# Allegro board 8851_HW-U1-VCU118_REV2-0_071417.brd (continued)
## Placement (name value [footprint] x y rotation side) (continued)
U53  SN74AVC1T45  [SC70_6]  131.13 15.57 180 top
U57  SI5328B  [QFN36_6X6MM]  85.08 23.6 270 top
U60  -  [MT40A256M16GE-083E]  74.76 38.64 270 bottom
U61  -  [MT40A256M16GE-083E]  74.76 66.84 270 bottom
U62  -  [MT40A256M16GE-083E]  74.76 95.03 270 bottom
U63  -  [MT40A256M16GE-083E]  74.76 80.93 270 bottom
U64  -  [MT40A256M16GE-083E]  74.76 52.74 270 bottom
U71  NC7SV125  [SC70_5]  190.97 168.46 90 bottom
U80  TCA9548APWR  [TSSOP_24]  138.89 119.9 180 top
U104  SI53340-B-GM  [QFN16_SI_3X3MM]  106.39 23.87 90 top
U109  NVT2008PW  [TSSOP_20]  26.73 120.91 270 bottom
U111  XC7Z010CLG225  [CL225]  15.9 134.57 270 top
U114  N25Q128A  [SO16_50P300X413]  18.61 110.08 270 bottom
U115  -  [DIGILENT_USB_JTAG_2_NC]  13.65 162.11 180 top
U122  SI5335A-B02436-GM  [QFN24_4X4MM]  164.54 19.5 270 top
U123  FS1-Z38-20Z6-10  [ON_AMP_FSI_Z38_20Z6_10]  50.72 51.21 270 top
U124  MAX15053  [WLP_9]  13.9 117.79 0 top
U125  MAX15027  [TDFN_10_3X3_EP]  39.5 106.17 180 bottom
U128  MAX16050  [TQFN_28_EP]  31.75 110.95 90 bottom
U131  MAX8892EXK+T  [SC70_5]  10.85 67.41 0 bottom
U132  NC7SZ66P5X  [SC70_5]  139.64 153.77 270 bottom
U133  MT25QU01  [SO16_50P300X413]  150.37 21.74 0 top
U134  TPS51200DRCT  [SON10_TPS51200]  146.59 103.62 270 bottom
U135  -  [MT40A256M16GE-083E]  161.16 48.76 270 top
U136  -  [MT40A256M16GE-083E]  161.16 62.86 270 top
U137  -  [MT40A256M16GE-083E]  161.16 76.95 270 top
U138  -  [MT40A256M16GE-083E]  161.16 91.05 270 top
U139  -  [MT40A256M16GE-083E]  161.16 34.41 270 top
U141  MT44K16M36RB_093  [FBGA168_13_5X13_5MM]  93.73 116.82 0 top
U142  MT44K16M36RB_093  [FBGA168_13_5X13_5MM]  75.82 116.67 270 top
U143  TPS51200DRCT  [SON10_TPS51200]  57.17 132.57 270 bottom
U145  FS1-Z38-20Z6-10  [ON_AMP_FSI_Z38_20Z6_10]  50.72 25.63 270 top
U150  MAX15301  [TQFN_32_EP]  45.19 122.3 270 bottom
U151  MAX15053  [WLP_9]  59.67 120.84 0 top
U154  MAX13035E  [TQFN_16]  7.04 165.63 0 bottom
U155  REF3012AIDBZT  [SOT23_3]  26.21 139.19 180 top
U156  MAX15301  [TQFN_32_EP]  188.68 26.77 0 bottom
U157  SI53340-B-GM  [QFN16_SI_3X3MM]  175.11 16.32 180 top
U159  VT1697SBFQX  [HPQFN_19_A]  213.96 117.17 180 top
U160  VT1697SBFQX  [HPQFN_19_A]  213.96 106.76 180 top
U161  VT1697SBFQX  [HPQFN_19_A]  213.96 96.35 180 top
U162  VT1697SBFQX  [HPQFN_19_A]  187.56 63.25 90 top
U163  VT1697SBFQX  [HPQFN_19_A]  147.49 140.49 180 top
U164  MAX20751EKX  [QFN_36_C]  235.17 109.21 270 bottom
U165  MAX20751EKX  [QFN_36_C]  178.04 46.67 90 top
U166  MAX20751EKX  [QFN_36_C]  165.69 137.19 180 top
U167  MAX8869EUE18+  [TSSOP_16_EP]  138.68 107.11 270 top
X1  TPD4S012  [DRY_6_SON]  7.99 70.76 90 bottom
X2  25.00MHZ  [XTAL_ABM8]  29.33 144.55 270 top
X5  114.285MHZ  [XTAL_CS_023_125X98]  82.3 29.58 180 top
X6  25MHZ  [XTAL_EPSON_FA238]  166.32 24.45 180 top
X7  TPD4S012  [DRY_6_SON]  7.99 83.58 90 bottom
Z1  -  [0603_SHORT]  211.93 66.72 0 top
Z2  -  [0201_SHORT]  204.56 58.6 180 bottom
Z3  -  [0201_SHORT]  204.56 59.23 180 bottom
Z4  -  [0201_SHORT]  144.72 31.82 90 bottom
Z5  -  [0201_SHORT]  145.41 31.8 90 bottom
Z6  -  [0402_SHORT]  190.26 112.71 90 top
Z7  -  [0402_SHORT]  188.99 112.71 90 top
Z8  -  [0201_SHORT]  179.07 35.43 0 bottom
Z14  -  [0201_SHORT]  151.76 87.91 180 bottom
Z15  -  [0603_SHORT]  181.01 135.31 180 top
Z16  -  [0201_SHORT]  151.76 88.67 180 bottom
Z43  -  [0201_SHORT]  84.71 99.24 270 top
Z65  -  [0201_SHORT]  188.37 143.69 0 bottom
Z66  -  [0201_SHORT]  188.37 143.05 0 bottom
Z86  -  [0201_SHORT]  163.45 99.87 180 top
Z87  -  [0201_SHORT]  93.73 106.6 0 bottom
Z88  -  [0603_SHORT]  42.98 122.45 90 top
Z89  -  [0201_SHORT]  50.04 113.94 270 bottom
Z90  -  [0201_SHORT]  49.28 113.94 270 bottom
Z91  -  [0201_SHORT]  104.7 115.93 180 bottom
Z92  -  [0201_SHORT]  104.7 116.7 180 bottom
Z93  -  [0603_SHORT]  161.09 115.03 270 top
Z94  -  [0603_SHORT]  216.31 45.77 180 top
Z96  -  [0603_SHORT]  185.5 34.51 0 bottom
Z97  -  [0201_SHORT]  152.78 122.35 90 bottom
Z98  -  [0201_SHORT]  153.54 122.35 90 bottom
Z101  -  [0201_SHORT]  143 98.73 270 bottom
Z102  -  [0201_SHORT]  142.24 98.73 270 bottom
Z103  -  [0201_SHORT]  223.68 54.15 0 bottom
Z104  -  [0201_SHORT]  223.68 53.52 0 bottom
Z107  -  [0201_SHORT]  151.74 87.24 180 bottom
Z108  -  [0201_SHORT]  151.74 86.48 180 bottom
Z115  -  [0201_SHORT]  40.39 99.49 90 top
Z116  -  [0201_SHORT]  39.34 99.52 90 top
Z117  -  [0201_SHORT]  190.76 52.43 0 bottom
Z118  -  [0201_SHORT]  190.76 51.63 0 bottom
Z119  -  [0603_SHORT]  234.44 112.57 90 top
Z120  -  [0603_SHORT]  175.52 46.69 90 bottom
Z121  -  [0603_SHORT]  165.67 134.66 180 bottom
Z128  -  [0402_SHORT]  140.46 103.3 180 bottom
Z129  -  [0402_SHORT]  140.46 102.03 180 bottom
Z130  -  [0402_SHORT]  140.08 30.91 180 top
Z131  -  [0402_SHORT]  140.08 32.18 180 top
Z132  -  [0402_SHORT]  132.59 102.41 180 bottom
Z133  -  [0402_SHORT]  132.59 101.14 180 bottom

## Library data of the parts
B1 = TS518FE_FL35E
C1 = 0_1UF_0402: tolerance: 10%; room: SYSACE
C2 = 0_1UF_0402: tolerance: 10%; room: DDR3
C3 C193 C866 C1348-C1352 C1554-C1556 C1605-C1620 = 22UF_1206: tolerance: 10%
C4 C856 C858 C1331 C1332 = DNP_C_0402_25_ROUND: User Part Number: USERPART#
C5-C7 C25-C27 C39-C41 C62-C66 C69 C70 C76 C86 C87 C90 C93 C104-C108 C117 C121-C123 C125-C127 C138 C150 C152 C155 C158 C235 C236 C239 C501 C522 C525 C527 C540 C543 C549-C551 C555-C560 C633 C640 C650 C651 C695-C700 C774 C775 C780 C848-C853 C864 C865 C893 C894 C953-C955 C1142-C1162 C1232 C1233 C1235-C1247 C1303-C1306 C1342-C1347 C1361 C1363 C1364 C1395 C1396 C1551-C1553 C1566 C1567 C1580 C1581 C1584-C1604 C1759 = 0_1UF_0402: tolerance: 10%
C8 C11 C12 C234 = 22UF_0603: tolerance: 20%
C9 C10 = 0_01UF_0402: tolerance: 10%; room: DDR3
C13 C14 = 0_01UF_0402: tolerance: 10%; signal model: 0_1UF_0402_0.1UF
C15 C23 C24 C28 = 0_1UF_0402: tolerance: 10%; room: PCIE
C16 C67 C81-C84 C102 C118 C119 C175 C198-C204 C207-C214 C217-C225 C241 C243-C245 C324 C370 C639 C871 C872 C1163 C1318 C1356 C1397 C1398 C1446 C1447 C1449 = 0_01UF_0402: tolerance: 10%
C17-C22 C29-C38 C42-C52 C56 C58-C61 C614 C615 C618 C619 C622 C623 C1504 C1506 C1515-C1520 C1523 C1524 C1526 C1703 C1704 = 0_22UF_0402: tolerance: 10%; signal model: 0_22UF_0402_0.22UF
C53 = 0_1UF_0402: tolerance: 10%; room: DVI
C54 C55 C57 C73 C74 C120 C128 C149 C154 C157 C162 C1582 C1583 = 0_1UF_0402: tolerance: 10%; room: USB-UART
C68 C242 C1632 C1633 = 10UF_1210: tolerance: 10%
C71 C72 = 0_1UF_0402: tolerance: 10%; signal model: 0_22UF_0402_0.22UF; room: USB-UART
C75 = 0_1UF_0402: tolerance: 10%; room: LCD
C77 C85 = 0_1UF_0402: tolerance: 10%; signal model: 0_1UF_0402_0.1UF
C78-C80 C132 C145 C423 C794 C1313 C1408 C1409 C1411 C1625-C1631 C1731 = 10UF_0603: tolerance: 20%
C88 C89 = 0_01UF_0402: tolerance: 10%; signal model: 0_22UF_0402_0.22UF; room: PWRCTL2
C91 = 0_1UF_0402: tolerance: 10%; signal model: 0_22UF_0402_0.22UF; room: PWRMGTAVCC
C92 C98 = 0_1UF_0402: tolerance: 10%; room: USB-UART; signal model: 0_22UF_0402_0.22UF
C94 = 0_01UF_0402: tolerance: 10%; signal model: 0_22UF_0402_0.22UF; room: PWRMGTAVTT
C95 C101 = 0_01UF_0402: tolerance: 10%; signal model: 0_22UF_0402_0.22UF
C96 C97 C99 = 0_1UF_0402: tolerance: 10%; signal model: 0_22UF_0402_0.22UF
C100 = 0_01UF_0402: tolerance: 10%; signal model: 0_22UF_0402_0.22UF; room: USBJTAG
C103 C109-C116 C191 C228 C873 C874 C1362 C1677-C1681 = 1UF_0402: tolerance: 10%
C124 C172 C173 C226 C227 C288-C290 C294 C298 C346 C701 C891 C892 C910 C1011-C1013 C1317 C1441-C1443 C1445 C1641-C1676 C1753 = 1UF_0603: tolerance: 10%
C129 C133-C137 C139-C142 C237 C238 C1781 = 0_1UF_X7R_50V_0402: tolerance: 10%
C130 C258 C1311 C1401 C1402 C1404 = 2_2UF_0402: tolerance: 10%
C131 C174 C194 C895 C896 C905 C956 C957 C1406 C1407 = 100UF_1210: tolerance: 20%
C143 C144 = 18PF_0402: tolerance: 5%
C146 C257 C1314 C1412 C1413 C1415 C1634-C1636 = 2_2UF_0805: tolerance: 10%
C147 C148 C215 C216 C1315 C1316 C1429-C1432 C1437-C1440 = 22UF_1210: tolerance: 10%
C151 C195 = 22UF_1206: tolerance: 10%; room: USB-UART
C153 = 100UF_1206: tolerance: 20%; room: PWRVCC1V5
C156 C161 C166-C171 C205 C246-C248 C792 C795 C796 C1487 C1488 = 47UF_1210: tolerance: 20%
C159 C176-C182 C249-C255 C331 C334 C348-C354 C356 C589 C590 C595 C596 C601-C604 C657-C659 C702-C707 C711 C713 C798 C801 C803 C805 C806 C808 C810 C811 C919-C924 C1052-C1054 C1164-C1182 C1269-C1273 C1450-C1455 C1462-C1467 C1474-C1481 C1483-C1485 C1505 C1557-C1559 C1568-C1577 C1755 C1756 = 4_7UF_0402: tolerance: 20%
C160 = 4_7UF_0402: tolerance: 20%; room: ETHERNET
C163-C165 C196 C788-C791 C816 C902 C903 C906-C909 C914 C916-C918 C1419-C1421 C1423-C1428 C1486 C1732-C1752 C1757 C1758 = 100UF_1206: tolerance: 20%
C183 C229 C358 C869 C870 C1683-C1685 C1688-C1691 C1694 C1695 C1698 C1699 C1754 = DNP_C_0402
C184 C231 C406 C1325 C1700-C1702 = 0_22UF_0402: tolerance: 10%
C185 C240 C454 C1527 C1528 C1530 = 2200PF_0402: tolerance: 10%
C186 C187 C369 C729 C1328 C1329 C1531-C1534 C1537 C1538 = 0_15UF_0402: tolerance: 10%
C188 C740 C1330 C1539 C1540 C1712-C1718 C1724 = 100PF_0402: tolerance: 10%
C189 C470 C480 C1336 C1543 C1544 C1546 = 4_7UF_0603: tolerance: 10%
C190 C862 C1637-C1639 = 0_022UF_0402: tolerance: 10%
C192 C876 = 4_7UF_0805: tolerance: 10%
C197 = 100UF_1206: tolerance: 20%; room: USB-UART
C206 C230 C911 C915 = 470UF_G: tolerance: 20%
C232 C451 C1208 C1289 C1327 C1542 C1705-C1709 = 1000PF_0402: tolerance: 10%
C233 C1778-C1780 = DNP_C_0603
C295 C1640 = 1UF_0603: tolerance: 10%; room: USB-UART
C330 C460-C462 = 680UF_TANT_X_HITEMP: tolerance: 20%
C434-C441 C716-C723 C1070-C1073 C1188-C1207 C1277 C1279-C1288 C1298 = 0_068UF_0402: tolerance: 10%
C466 C467 C1108 C1109 = 100PF_0805: tolerance: 5%
C491-C498 C628 C630 C632 C749-C756 C820-C822 C825 C828 C830 C833-C835 C837 C841-C844 C1138-C1141 C1209-C1228 C1290-C1296 C1299-C1301 C1391 C1392 C1547-C1550 C1578 C1579 = 0_47UF_0402: tolerance: 10%
C499 = 330UF_8_3MMX8_3MM: tolerance: 20%
C500 C516-C520 C913 C1183-C1187 C1386-C1390 = 10UF_0805: tolerance: 10%
C859 = 0_1UF_0402: tolerance: 10%; room: PWR_DIGIT
C867 C868 C1353 C1354 C1621-C1624 = 47UF_1206: tolerance: 20%
C878 C1358 = 5600PF_0805: tolerance: 10%
C879 C1359 = 560PF_0402: tolerance: 10%
C1719 = 6800PF_0402: tolerance: 10%
C1720 C1721 = 22PF_0402: tolerance: 5%
C1722 C1723 = 8200PF_0805: tolerance: 10%
C1725 = 220PF_0402: tolerance: 10%
D4 D5 D7 D10-D14 D17 D35 = BAT54T1G
D8 D33 D36-D38 = MMSZ4680T1G_SOD_123
D9 D16 D19 D32 D39 = MMSZ4683T1G
D15 = BAS40_04_SOT23
DS1 DS4 DS15-DS17 DS19 DS24 DS25 DS27 DS28 DS46 DS49 = HSMY-C190: Tolerance: TOL; User Part Number: PARTNO
DS2 = HSMF-C155: room: PWRCTL1
DS3 DS42 = HSMF-C155
DS5 DS21 DS36 DS47 DS48 = HSMY-C190: User Part Number: PARTNO; Tolerance: TOL
DS6-DS8 DS43 DS44 = LED-GRN-SMT_LED_0603: Tolerance: TOL; User Part Number: PARTNO
DS9 DS12 DS13 DS18 DS20 DS26 = LED-GRN-SMT_LED_0603: User Part Number: PARTNO; Tolerance: TOL
DS10 = LED-GRN-SMT_LED_0603: User Part Number: PARTNO; Tolerance: TOL; room: GPIO
DS14 = HSMY-C190: Tolerance: TOL; User Part Number: PARTNO; room: GPIO
DS34 = LED-BLUE-SMT: Tolerance: TOL; User Part Number: PARTNO
DS45 = LED-RED-SMT_LED_0603: Tolerance: TOL; User Part Number: PARTNO
EMICAGE1 = EMI_CAGE
J1 J96 = U95-T1Y1-100A
J2 = ASP_134486_01
J3 = MOLEX-87832-1420
J4 J106 = ZX62D_AB_5P8
J5 = HDR_1X3
J6 = SAMTEC_FIREFLY_RECEPT: room: PWRCTL1
J7 = HDR_2X4
J8 J9 J110 = HDR_1X2
J10 = 7499111221A
J11 J13 J16-J21 J28 J54 J58 J63 J65 J70 J86 J88 J97 J99-J101 J103 J104 J107-J109 = TP_5000_RED
J12 J14 = HDR_1X2: room: PWRCTL2
J15 = 39-30-1060_JACK_500X540: room: LCD
J22 = ASP_184329_01: room: USBJTAG
J23-J27 J38 = TP_5001_BLACK
J30-J35 = SMA_32K10K-400
J36 J73 = WM2701-ND
J39 = SHR_HDR_2X8: room: USB
J52 = HDR_2X6_F_RA
J53 = HDR_2X6
J78 = HDR_1X4
J82 = SAMTEC_1X6_RA_0190
J83 = CON_MOL_10P_5025700893
J105 = HDR_1X6
L1 L70-L72 L86 = 74479787210B_1008: tolerance: 20%
L2 = 74479787210B_1008: tolerance: 20%; room: DVI
L3 L7 L80 = INDUCTOR_1_0UH: tolerance: 20%
L4 L5 = 1_0UH_INDUCTOR_IHLP2525AH: tolerance: 20%
L6 L22 L65 L76 L77 L79 L90 L91 = FERRITE-96: tolerance: XXX
L8 L48 L67 L82 L83 L85 = INDUCTOR_10UH: tolerance: 20%
L13 L60 L61 L87 = FERRITE-600: tolerance: XXX
L31 L93 L94 = FERRITE-220_0603: tolerance: XXX
L34 L35 = FERRITE-220_0603: tolerance: XXX; room: USB-UART
L62 = FERRITE-120_0603: tolerance: XXX
L63 = INDUCTOR_1_2UH: tolerance: 20%
L66 L74 = INDUCTOR_744311068: tolerance: 20%
L73 = INDUCTOR_3_3UH: tolerance: 20%
L75 = INDUCTOR_680NH_7443320068: tolerance: 20%
L88 L89 = INDUCTOR_744311022: tolerance: 20%
L92 = FERRITE-835: tolerance: XXX
L95 = CLB1108: tolerance: TBD
L96-L98 = 3_3UH_TDK_IND: tolerance: 20%
MH1-MH7 = HOLE_MH_125_250
Q1 = FDS6681Z: room: PWRCTL1
Q2 Q3 Q5-Q8 Q10-Q18 Q21-Q24 Q27 Q28 Q34-Q37 Q41 Q52-Q57 Q59 Q60 = RUM001L02T2CL_SOT723
Q4 = BSS138
Q9 Q19 Q39 Q42 Q43 = FDPC8011S
Q20 Q25 Q40 Q48 Q49 Q51 = MMBT3904T
Q26 Q58 = NDS331N_SOT23
Q45 Q47 = FDMS8558S
Q61 = SI2300DS_SOT23
R1 R2 R6 R13 R28 R29 R31 R53 R86 R96 R97 R107 R126 R191 R192 R208 R213 R217 R218 R333 R422 R724 R726-R730 R792 R793 R826 R854-R858 R888 R934 R1016 R1018-R1020 R1092 R1094 R1095 R1101 R1124 R1327 = 4_70K_0402: tolerance: 1%
R3 R796 R798 R1023 R1024 = DNP_R_0402_25_ROUND: User Part Number: USERPART#
R4 R5 R7 R108 R377-R380 R383-R386 R700 R704 R705 R893 R930-R933 R1001 R1002 R1071-R1073 = 240_0402: tolerance: 1%
R8 R9 = 100_0402: tolerance: 1%; room: GPIO
R10 R83 R133 R135 R573-R575 R810-R812 = 15_0402: tolerance: 1%
R11 R12 R54-R57 R60-R68 R70 R140 R141 R193 R215 R220-R223 R229 R318 R319 R345 R346 R352 R354-R356 R362 R418 R547 R580-R582 R801 R802 R860 R891 R892 R1017 R1070 R1103 R1104 R1143 R1144 R1199 R1200 R1235 R1241 R1244 R1247 R1248 R1251 R1252 R1328 = DNP_R_0402
R14 R167 R1021 R1111 R1113 R1116 R1208-R1212 = 10_0402: tolerance: 1%
R15 R38 R88 R150 R174-R176 R194 R195 R197 R266 R299 R300 R687 R692 R900 R901 R988 R989 R991 R992 R1088 R1140-R1142 R1177 R1198 R1326 = 100_0402: tolerance: 1%
R16 R39 R44 R105 R106 R125 R128-R130 R162-R164 R210-R212 R219 R308 R316 R321 R323 R324 R327 R331 R334 R639 R816-R821 R823 R824 R859 R861 R890 R1192-R1195 R1288 = 10_0K_0402: tolerance: 1%
R17 R18 R20 R22-R25 R35 R42 R45-R52 R69 R71 R73 R156 R177-R188 R205 R206 R273 R424 R434 R435 R548 R560 R594-R597 R640 R896 R1074 R1154 R1155 R1157 R1291 = 1_00K_0402: tolerance: 1%
R19 R115 = 4_70K_0402: tolerance: 1%; room: PWRMGTAVCC
R21 = 4_70K_0402: tolerance: 1%; room: PWRDDR3
R26 R27 = 2_21K_0402: tolerance: 1%
R30 = 4_70K_0402: tolerance: 1%; room: PCIE
R32 R563 R799 = 24_9_0402: tolerance: 1%
R33 R81 R82 R127 R143-R149 R151 R472 R473 R478-R484 R486-R488 R492 R784-R787 R945 R1013 R1183 = 261_0402: tolerance: 1%
R34 = 2_21K_0402: tolerance: 1%; room: PCIE
R36 R37 = 100_0402: tolerance: 1%; room: PCIE
R40 = 1_00K_0402: tolerance: 1%; room: PCIE
R41 = 1_00K_0402: tolerance: 1%; room: ETHERNET
R43 R1190 R1214 = 432_0402: tolerance: 1%
R58 R59 R91-R94 R189 R190 R498-R502 R600-R604 R607 R608 R611-R614 R617 R618 R621-R630 R682 R683 = 4_99K_0402: tolerance: 1%
R72 R75 = 4_99K_0402: tolerance: 1%; room: FLASH
R74 = 9_53K_0402: tolerance: 1%
R76 = 1_00K_0402: tolerance: 1%; room: FLASH
R77 = 4_70K_0402: tolerance: 1%; room: FLASH
R78 R79 R99-R104 R109-R114 = 10_0201: tolerance: 1%
R80 R712 R1127 = 1_43K_0402: tolerance: 1%
R84 = 1_0M_0402: tolerance: 5%
R85 R89 R90 R131 R132 R142 = 200K_0402: tolerance: 1%
R87 = WSLP12065L000FEA: tolerance: 1%; room: FLASH
R95 = 10_0402: tolerance: 1%; room: FLASH
R98 R154 R216 R399 R803 R804 R1022 R1112 R1114 R1147 R1148 R1230-R1232 R1253-R1258 R1324 R1325 = 0_0402: tolerance: 5%
R116 = 4_70K_0402: tolerance: 1%; room: PWRMGTAVTT
R117-R124 R236 = 4_70K_0201: tolerance: 1%
R134 R157 R158 R165 R421 R460 R463 R464 R467 R468 R830 R1075 R1076 R1158-R1161 R1164 R1165 = 2_00K_0402: tolerance: 1%
R136 R214 R1028 R1096 R1130-R1133 = 12_7K_0402: tolerance: 1%
R137 R832 R1078 R1108 = 26_1K_0402: tolerance: 1%
R138 R1289 = 8_06K_0402: tolerance: 1%
R139 R231 R1029 R1136 R1137 R1139 = 2_2_0603: tolerance: 1%
R152 R161 R172 R173 R1171 R1172 = WSLP12065L000FEA: tolerance: 1%
R153 R1203 R1204 = 0_001_CSNL1206FT1L00: tolerance: 1%
R155 = 14_7K_0402: tolerance: 1%
R159 R515 R1077 R1166 R1167 R1169 = 140K_0402: tolerance: 1%
R160 R1290 = 10_2K_0402: tolerance: 1%
R166 = 34_0K_0402: tolerance: 1%
R168 = CSS2725FTL500: tolerance: 1%
R169 R259 R899 R1222-R1227 = 499_0402: tolerance: 1%
R170 R1317-R1319 = DNP_R_0805
R171 R1267-R1271 = 3_01K_0402: tolerance: 1%
R196 R1275-R1279 = 4_7_0402: tolerance: 1%
R198 R201 R203 = 11_0K_0402: tolerance: 1%
R199 R1125 = 38_3K_0402: tolerance: 1%
R200 R202 R204 R1233 R1234 = 2_49K_0402: tolerance: 1%
R237-R247 R249-R257 R564 R567-R569 R902-R921 R923-R926 R952-R978 R990 R1105 R1106 = 39_2_0201: tolerance: 1%
R258 R922 = 402_0201: tolerance: 1%
R388 R389 R928 R929 R1008 R1009 = 100K_0402: tolerance: 1%
R553 R554 R1201 = 200_0402: tolerance: 1%
R556-R559 R706-R709 R894 R895 R935-R944 = 100_0201: tolerance: 1%
R565 R566 R897 R898 R951 R1292 = 36_0402: tolerance: 1%
R598 R1237 = 220_0402: tolerance: 1%
R637 = 1_50K_0402: tolerance: 1%
R638 R815 = 3_32K_0402: tolerance: 1%
R748 = 333_0402: tolerance: 1%
R756 R1052 = 1_78K_0402: tolerance: 1%
R772-R776 R827 R828 R1100 R1196 R1197 = 20K_0402: tolerance: 1%
R805 R1090 = 4_02K_0402: tolerance: 1%
R808 = 5_9K_0402: tolerance: 1%
R809 = 4_32K_0402: tolerance: 1%
R813 R1097 = 3_65K_0402: tolerance: 1%
R814 = 2_67K_0402: tolerance: 1%
R837-R841 = 68_1_0402: tolerance: 1%
R1007 R1145 = 249_0402: tolerance: 1%
R1015 R1293 = 2_40K_0402: tolerance: 1%
R1079 R1107 = 953_0402: tolerance: 1%
R1083-R1085 R1087 = 1_21K_0402: tolerance: 1%
R1109 = 68_1K_0402: tolerance: 1%
R1126 = 21_5K_0402: tolerance: 1%
R1135 = 6_19K_0402: tolerance: 1%
R1170 = 51_1K_0402: tolerance: 1%
R1174 = 59_0K_0402: tolerance: 1%
R1205 = 115_0402: tolerance: 1%
R1206 R1207 = 80_6_0402: tolerance: 1%
R1213 = 576_0402: tolerance: 1%
R1215 = 1_80K_0402: tolerance: 1%
R1216-R1218 = 29_4K_0402: tolerance: 1%
R1219-R1221 = 2_15K_0402: tolerance: 1%
R1228 = 100_1206: tolerance: 1%
R1229 = 24_9K_0402: tolerance: 1%
R1236 = 82_5_0402: tolerance: 1%
R1238-R1240 = 20_0K_0402: tolerance: 0.5%
R1259 = 820_0402: tolerance: 1%
R1260 = 680_0402: tolerance: 1%
R1261 = 402_0402: tolerance: 1%
R1262-R1264 = 332_0402: tolerance: 1%
R1265 = 15K_0402: tolerance: 1%
R1266 = 22_1K_0402: tolerance: 1%
R1272-R1274 = 604_0402: tolerance: 1%
R1280 R1281 = 1_02K_0402: tolerance: 1%
RP2 RP3 = 10KX4_0603X4: tolerance: 5%
SW1 = 1101M2S3AQE2
SW4 SW6 SW7 SW9 SW10 SW14 SW17 = TL3301EF100QG-ND
SW5 = TL3301EF100QG-ND: room: NSEWGPIO
SW12 SW15 SW16 = 218-4LPSTRF
U1 = SOC_VU9P_FLGA2104_IRONWOOD: room: FPGA
U2 = PCIE_16LANE_EDGE
U3 U17 U41 U42 U44 U109 = NVT2008PW
U4 U6 U30 U150 U156 = MAX15301
U5 U167 = MAX8869EUE18
U7 = DP83867ISRGZ
U8 U23 U27 U29 U35-U37 = INA226
U9 = MAX15301: room: PCIE
U10 U125 = MAX15027
U11 U159-U163 = VT1697SBFQX
U12 = M24C08-WDW6TP: room: PWRMGTAVCC
U13 U22 U33 = SN74AVC2T245
U14 = SG5032: tolerance: 50PPM
U15 = MAX16052: room: DVI
U16 = BNX016-01: room: USB
U18 U32 U38 = 570BAB000544DG_5X7: tolerance: 50PPM
U19 U51 = SN74AVC8T245
U20 U21 U40 = ICS85411AMLF
U24 = TPS51200DRCT: room: PWRCTL1
U25 = SN74LVC1G08
U26 U132 = NC7SZ66
U28 U80 = TCA9548APWR_TSSOP_24
U31 = MAX6643
U34 = CP2105
U39 = ICS854S006I
U43 U133 = MT25QU01
U53 = SN74AVC1T45
U57 = SI5328B-C-GMR
U60-U64 U135-U139 = MT40A256M16GE-083E
U71 = NC7SV125
U104 U157 = SI53340-B-GM
U111 = XC7Z010CLG225
U114 = N25Q128A
U115 = DIGILENT_USB_JTAG_2_NC
U122 = SI5335A-B02436-GM
U123 U145 = FS1-Z38-20Z6-10
U124 U151 = MAX15053
U128 = MAX16050
U131 = MAX8892EXKT_SC70_5
U134 U143 = TPS51200DRCT
U141 U142 = MT44K16M36RB_093E
U154 = MAX13035E
U155 = REF3012AIDBZT_SOT23_3
U164-U166 = MAX20751EKX
X1 X7 = TPD4S012
X2 = XTAL_ABM8: tolerance: 40PPM
X5 = XTAL_CS_023_125X98: tolerance: 20PPM
X6 = 25MHZ_FA238: tolerance: 50PPM
Z1 Z15 Z88 Z93 Z94 Z96 Z119-Z121 = 0603_SHORT
Z2-Z5 Z8 Z14 Z16 Z43 Z65 Z66 Z86 Z87 Z89-Z92 Z97 Z98 Z101-Z104 Z107 Z108 Z115-Z118 = 0201_SHORT
Z6 Z7 Z128-Z133 = 0402_SHORT

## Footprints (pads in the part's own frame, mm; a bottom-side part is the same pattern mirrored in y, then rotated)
5MM_3_2MM_6P
  rect 0.889x1.6 smd: 1(-1.27,-1.3) 2(0,-1.3) 3(1.27,-1.3) 4(1.27,1.3) 5(0,1.3) 6(-1.27,1.3)
32K10K_400_3VIA
  round 1.397 smd: 1(0,0)
  round 2.413 hole 1.6: 2(-2.54,2.54) 3(-2.54,-2.54) 4(2.54,2.54) 5(2.54,-2.54)
0201
  rect 0.381x0.381 smd: 1(-0.292,0) 2(0.292,0)
0201_SHORT
  rect 0.381x0.381 smd: 1(-0.292,0)
  custom 0.089x0.089 smd: 2(0.292,0)
0402
  rect 0.508x0.635 smd: 1(-0.5,0) 2(0.5,0)
0402_SHORT
  rect 0.508x0.635 smd: 1(-0.5,0)
  custom 0.159x0.159 smd: 2(0.5,0)
0603
  rect 1.092x1.016 smd: 1(-0.794,0) 2(0.794,0)
0603_SHORT
  rect 1.092x1.016 smd: 1(-0.851,0)
  custom 0.254x0.254 smd: 2(0.851,0)
0805
  rect 1.397x1.321 smd: 1(-0.946,0) 2(0.946,0)
1008
  rect 2.21x0.787 smd: 1(0,-1) 2(0,1)
1206
  rect 1.651x1.88 smd: 1(-1.632,0) 2(1.632,0)
1210
  rect 1.524x2.54 smd: 1(-1.714,0) 2(1.714,0)
87832_1420
  round 1.016 hole 1.016 unplated: (-5,0) (5,0)
  rect 1.016x2.743 smd: 1(-6,-2.125) 2(-6,2.125) 3(-4,-2.125) 4(-4,2.125) 5(-2,-2.125) 6(-2,2.125) 7(0,-2.125) 8(0,2.125) 9(2,-2.125) 10(2,2.125) 11(4,-2.125) 12(4,2.125) 13(6,-2.125) 14(6,2.125)
7499111221A
  round 3.226 hole 3.226 unplated: (-6.35,0) (6.35,0)
  rect 1.524x1.524 hole 0.914: 1(5.075,15.24)
  round 1.524 hole 0.914: 2(3.045,15.24) 3(1.015,15.24) 4(-1.015,15.24) 5(-3.045,15.24) 6(-5.075,15.24) 7(6.095,17.78) 8(4.06,17.78) 9(2.025,17.78) 10(-2.025,17.78) 11(-4.06,17.78) 12(-6.095,17.78)
  round 1.524 hole 1.016: 13(6.12,20.32) 14(3.58,20.32) 15(-3.58,20.32) 16(-6.12,20.32)
  round 3.175 hole 1.575: SH1(-8.175,-3.18) SH2(8.175,-3.18)
ASP_134486_01
  round 1.27 hole 1.27 unplated: (-27.178,0) (27.178,-3.048)
  round 0.635 smd: A1(24.765,-5.715) A2(23.495,-5.715) A3(22.225,-5.715) A4(20.955,-5.715) A5(19.685,-5.715) A6(18.415,-5.715) A7(17.145,-5.715) A8(15.875,-5.715) A9(14.605,-5.715) A10(13.335,-5.715) A11(12.065,-5.715) A12(10.795,-5.715) A13(9.525,-5.715) A14(8.255,-5.715) A15(6.985,-5.715) A16(5.715,-5.715) A17(4.445,-5.715) A18(3.175,-5.715) A19(1.905,-5.715) A20(0.635,-5.715) A21(-0.635,-5.715) A22(-1.905,-5.715) A23(-3.175,-5.715) A24(-4.445,-5.715) A25(-5.715,-5.715) A26(-6.985,-5.715) A27(-8.255,-5.715) A28(-9.525,-5.715) A29(-10.795,-5.715) A30(-12.065,-5.715) A31(-13.335,-5.715) A32(-14.605,-5.715) A33(-15.875,-5.715) A34(-17.145,-5.715) A35(-18.415,-5.715) A36(-19.685,-5.715) A37(-20.955,-5.715) A38(-22.225,-5.715) A39(-23.495,-5.715) A40(-24.765,-5.715) B1(24.765,-4.445) B2(23.495,-4.445) B3(22.225,-4.445) B4(20.955,-4.445) B5(19.685,-4.445) B6(18.415,-4.445) B7(17.145,-4.445) B8(15.875,-4.445) B9(14.605,-4.445) B10(13.335,-4.445) B11(12.065,-4.445) B12(10.795,-4.445) B13(9.525,-4.445) B14(8.255,-4.445) B15(6.985,-4.445) B16(5.715,-4.445) B17(4.445,-4.445) B18(3.175,-4.445) B19(1.905,-4.445) B20(0.635,-4.445) B21(-0.635,-4.445) B22(-1.905,-4.445) B23(-3.175,-4.445) B24(-4.445,-4.445) B25(-5.715,-4.445) B26(-6.985,-4.445) B27(-8.255,-4.445) B28(-9.525,-4.445) B29(-10.795,-4.445) B30(-12.065,-4.445) B31(-13.335,-4.445) B32(-14.605,-4.445) B33(-15.875,-4.445) B34(-17.145,-4.445) B35(-18.415,-4.445) B36(-19.685,-4.445) B37(-20.955,-4.445) B38(-22.225,-4.445) B39(-23.495,-4.445) B40(-24.765,-4.445) C1(24.765,-3.175) C2(23.495,-3.175) C3(22.225,-3.175) C4(20.955,-3.175) C5(19.685,-3.175) C6(18.415,-3.175) C7(17.145,-3.175) C8(15.875,-3.175) C9(14.605,-3.175) C10(13.335,-3.175) C11(12.065,-3.175) C12(10.795,-3.175) C13(9.525,-3.175) C14(8.255,-3.175) C15(6.985,-3.175) C16(5.715,-3.175) C17(4.445,-3.175) C18(3.175,-3.175) C19(1.905,-3.175) C20(0.635,-3.175) C21(-0.635,-3.175) C22(-1.905,-3.175) C23(-3.175,-3.175) C24(-4.445,-3.175) C25(-5.715,-3.175) C26(-6.985,-3.175) C27(-8.255,-3.175) C28(-9.525,-3.175) C29(-10.795,-3.175) C30(-12.065,-3.175) C31(-13.335,-3.175) C32(-14.605,-3.175) C33(-15.875,-3.175) C34(-17.145,-3.175) C35(-18.415,-3.175) C36(-19.685,-3.175) C37(-20.955,-3.175) C38(-22.225,-3.175) C39(-23.495,-3.175) C40(-24.765,-3.175) D1(24.765,-1.905) D2(23.495,-1.905) D3(22.225,-1.905) D4(20.955,-1.905) D5(19.685,-1.905) D6(18.415,-1.905) D7(17.145,-1.905) D8(15.875,-1.905) D9(14.605,-1.905) D10(13.335,-1.905) D11(12.065,-1.905) D12(10.795,-1.905) D13(9.525,-1.905) D14(8.255,-1.905) D15(6.985,-1.905) D16(5.715,-1.905) D17(4.445,-1.905) D18(3.175,-1.905) D19(1.905,-1.905) D20(0.635,-1.905) D21(-0.635,-1.905) D22(-1.905,-1.905) D23(-3.175,-1.905) D24(-4.445,-1.905) D25(-5.715,-1.905) D26(-6.985,-1.905) D27(-8.255,-1.905) D28(-9.525,-1.905) D29(-10.795,-1.905) D30(-12.065,-1.905) D31(-13.335,-1.905) D32(-14.605,-1.905) D33(-15.875,-1.905) D34(-17.145,-1.905) D35(-18.415,-1.905) D36(-19.685,-1.905) D37(-20.955,-1.905) D38(-22.225,-1.905) D39(-23.495,-1.905) D40(-24.765,-1.905) E1(24.765,-0.635) E2(23.495,-0.635) E3(22.225,-0.635) E4(20.955,-0.635) E5(19.685,-0.635) E6(18.415,-0.635) E7(17.145,-0.635) E8(15.875,-0.635) E9(14.605,-0.635) E10(13.335,-0.635) E11(12.065,-0.635) E12(10.795,-0.635) E13(9.525,-0.635) E14(8.255,-0.635) E15(6.985,-0.635) E16(5.715,-0.635) E17(4.445,-0.635) E18(3.175,-0.635) E19(1.905,-0.635) E20(0.635,-0.635) E21(-0.635,-0.635) E22(-1.905,-0.635) E23(-3.175,-0.635) E24(-4.445,-0.635) E25(-5.715,-0.635) E26(-6.985,-0.635) E27(-8.255,-0.635) E28(-9.525,-0.635) E29(-10.795,-0.635) E30(-12.065,-0.635) E31(-13.335,-0.635) E32(-14.605,-0.635) E33(-15.875,-0.635) E34(-17.145,-0.635) E35(-18.415,-0.635) E36(-19.685,-0.635) E37(-20.955,-0.635) E38(-22.225,-0.635) E39(-23.495,-0.635) E40(-24.765,-0.635) F1(24.765,0.635) F2(23.495,0.635) F3(22.225,0.635) F4(20.955,0.635) F5(19.685,0.635) F6(18.415,0.635) F7(17.145,0.635) F8(15.875,0.635) F9(14.605,0.635) F10(13.335,0.635) F11(12.065,0.635) F12(10.795,0.635) F13(9.525,0.635) F14(8.255,0.635) F15(6.985,0.635) F16(5.715,0.635) F17(4.445,0.635) F18(3.175,0.635) F19(1.905,0.635) F20(0.635,0.635) F21(-0.635,0.635) F22(-1.905,0.635) F23(-3.175,0.635) F24(-4.445,0.635) F25(-5.715,0.635) F26(-6.985,0.635) F27(-8.255,0.635) F28(-9.525,0.635) F29(-10.795,0.635) F30(-12.065,0.635) F31(-13.335,0.635) F32(-14.605,0.635) F33(-15.875,0.635) F34(-17.145,0.635) F35(-18.415,0.635) F36(-19.685,0.635) F37(-20.955,0.635) F38(-22.225,0.635) F39(-23.495,0.635) F40(-24.765,0.635) G1(24.765,1.905) G2(23.495,1.905) G3(22.225,1.905) G4(20.955,1.905) G5(19.685,1.905) G6(18.415,1.905) G7(17.145,1.905) G8(15.875,1.905) G9(14.605,1.905) G10(13.335,1.905) G11(12.065,1.905) G12(10.795,1.905) G13(9.525,1.905) G14(8.255,1.905) G15(6.985,1.905) G16(5.715,1.905) G17(4.445,1.905) G18(3.175,1.905) G19(1.905,1.905) G20(0.635,1.905) G21(-0.635,1.905) G22(-1.905,1.905) G23(-3.175,1.905) G24(-4.445,1.905) G25(-5.715,1.905) G26(-6.985,1.905) G27(-8.255,1.905) G28(-9.525,1.905) G29(-10.795,1.905) G30(-12.065,1.905) G31(-13.335,1.905) G32(-14.605,1.905) G33(-15.875,1.905) G34(-17.145,1.905) G35(-18.415,1.905) G36(-19.685,1.905) G37(-20.955,1.905) G38(-22.225,1.905) G39(-23.495,1.905) G40(-24.765,1.905) H1(24.765,3.175) H2(23.495,3.175) H3(22.225,3.175) H4(20.955,3.175) H5(19.685,3.175) H6(18.415,3.175) H7(17.145,3.175) H8(15.875,3.175) H9(14.605,3.175) H10(13.335,3.175) H11(12.065,3.175) H12(10.795,3.175) H13(9.525,3.175) H14(8.255,3.175) H15(6.985,3.175) H16(5.715,3.175) H17(4.445,3.175) H18(3.175,3.175) H19(1.905,3.175) H20(0.635,3.175) H21(-0.635,3.175) H22(-1.905,3.175) H23(-3.175,3.175) H24(-4.445,3.175) H25(-5.715,3.175) H26(-6.985,3.175) H27(-8.255,3.175) H28(-9.525,3.175) H29(-10.795,3.175) H30(-12.065,3.175) H31(-13.335,3.175) H32(-14.605,3.175) H33(-15.875,3.175) H34(-17.145,3.175) H35(-18.415,3.175) H36(-19.685,3.175) H37(-20.955,3.175) H38(-22.225,3.175) H39(-23.495,3.175) H40(-24.765,3.175) J1(24.765,4.445) J2(23.495,4.445) J3(22.225,4.445) J4(20.955,4.445) J5(19.685,4.445) J6(18.415,4.445) J7(17.145,4.445) J8(15.875,4.445) J9(14.605,4.445) J10(13.335,4.445) J11(12.065,4.445) J12(10.795,4.445) J13(9.525,4.445) J14(8.255,4.445) J15(6.985,4.445) J16(5.715,4.445) J17(4.445,4.445) J18(3.175,4.445) J19(1.905,4.445) J20(0.635,4.445) J21(-0.635,4.445) J22(-1.905,4.445) J23(-3.175,4.445) J24(-4.445,4.445) J25(-5.715,4.445) J26(-6.985,4.445) J27(-8.255,4.445) J28(-9.525,4.445) J29(-10.795,4.445) J30(-12.065,4.445) J31(-13.335,4.445) J32(-14.605,4.445) J33(-15.875,4.445) J34(-17.145,4.445) J35(-18.415,4.445) J36(-19.685,4.445) J37(-20.955,4.445) J38(-22.225,4.445) J39(-23.495,4.445) J40(-24.765,4.445) K1(24.765,5.715) K2(23.495,5.715) K3(22.225,5.715) K4(20.955,5.715) K5(19.685,5.715) K6(18.415,5.715) K7(17.145,5.715) K8(15.875,5.715) K9(14.605,5.715) K10(13.335,5.715) K11(12.065,5.715) K12(10.795,5.715) K13(9.525,5.715) K14(8.255,5.715) K15(6.985,5.715) K16(5.715,5.715) K17(4.445,5.715) K18(3.175,5.715) K19(1.905,5.715) K20(0.635,5.715) K21(-0.635,5.715) K22(-1.905,5.715) K23(-3.175,5.715) K24(-4.445,5.715) K25(-5.715,5.715) K26(-6.985,5.715) K27(-8.255,5.715) K28(-9.525,5.715) K29(-10.795,5.715) K30(-12.065,5.715) K31(-13.335,5.715) K32(-14.605,5.715) K33(-15.875,5.715) K34(-17.145,5.715) K35(-18.415,5.715) K36(-19.685,5.715) K37(-20.955,5.715) K38(-22.225,5.715) K39(-23.495,5.715) K40(-24.765,5.715)
  round 3.2 hole 2.692: ST1(-31.496,2.007) ST2(31.496,2.007)
ASP_184329_01
  round 1.295 hole 1.321 unplated: (-27.19,0) (27.19,-3.05)
  round 0.635 smd: A1(24.765,-5.715) A2(23.495,-5.715) A3(22.225,-5.715) A4(20.955,-5.715) A5(19.685,-5.715) A6(18.415,-5.715) A7(17.145,-5.715) A8(15.875,-5.715) A9(14.605,-5.715) A10(13.335,-5.715) A11(12.065,-5.715) A12(10.795,-5.715) A13(9.525,-5.715) A14(8.255,-5.715) A15(6.985,-5.715) A16(5.715,-5.715) A17(4.445,-5.715) A18(3.175,-5.715) A19(1.905,-5.715) A20(0.635,-5.715) A21(-0.635,-5.715) A22(-1.905,-5.715) A23(-3.175,-5.715) A24(-4.445,-5.715) A25(-5.715,-5.715) A26(-6.985,-5.715) A27(-8.255,-5.715) A28(-9.525,-5.715) A29(-10.795,-5.715) A30(-12.065,-5.715) A31(-13.335,-5.715) A32(-14.605,-5.715) A33(-15.875,-5.715) A34(-17.145,-5.715) A35(-18.415,-5.715) A36(-19.685,-5.715) A37(-20.955,-5.715) A38(-22.225,-5.715) A39(-23.495,-5.715) A40(-24.765,-5.715) B1(24.765,-4.445) B2(23.495,-4.445) B3(22.225,-4.445) B4(20.955,-4.445) B5(19.685,-4.445) B6(18.415,-4.445) B7(17.145,-4.445) B8(15.875,-4.445) B9(14.605,-4.445) B10(13.335,-4.445) B11(12.065,-4.445) B12(10.795,-4.445) B13(9.525,-4.445) B14(8.255,-4.445) B15(6.985,-4.445) B16(5.715,-4.445) B17(4.445,-4.445) B18(3.175,-4.445) B19(1.905,-4.445) B20(0.635,-4.445) B21(-0.635,-4.445) B22(-1.905,-4.445) B23(-3.175,-4.445) B24(-4.445,-4.445) B25(-5.715,-4.445) B26(-6.985,-4.445) B27(-8.255,-4.445) B28(-9.525,-4.445) B29(-10.795,-4.445) B30(-12.065,-4.445) B31(-13.335,-4.445) B32(-14.605,-4.445) B33(-15.875,-4.445) B34(-17.145,-4.445) B35(-18.415,-4.445) B36(-19.685,-4.445) B37(-20.955,-4.445) B38(-22.225,-4.445) B39(-23.495,-4.445) B40(-24.765,-4.445) C1(24.765,-3.175) C2(23.495,-3.175) C3(22.225,-3.175) C4(20.955,-3.175) C5(19.685,-3.175) C6(18.415,-3.175) C7(17.145,-3.175) C8(15.875,-3.175) C9(14.605,-3.175) C10(13.335,-3.175) C11(12.065,-3.175) C12(10.795,-3.175) C13(9.525,-3.175) C14(8.255,-3.175) C15(6.985,-3.175) C16(5.715,-3.175) C17(4.445,-3.175) C18(3.175,-3.175) C19(1.905,-3.175) C20(0.635,-3.175) C21(-0.635,-3.175) C22(-1.905,-3.175) C23(-3.175,-3.175) C24(-4.445,-3.175) C25(-5.715,-3.175) C26(-6.985,-3.175) C27(-8.255,-3.175) C28(-9.525,-3.175) C29(-10.795,-3.175) C30(-12.065,-3.175) C31(-13.335,-3.175) C32(-14.605,-3.175) C33(-15.875,-3.175) C34(-17.145,-3.175) C35(-18.415,-3.175) C36(-19.685,-3.175) C37(-20.955,-3.175) C38(-22.225,-3.175) C39(-23.495,-3.175) C40(-24.765,-3.175) D1(24.765,-1.905) D2(23.495,-1.905) D3(22.225,-1.905) D4(20.955,-1.905) D5(19.685,-1.905) D6(18.415,-1.905) D7(17.145,-1.905) D8(15.875,-1.905) D9(14.605,-1.905) D10(13.335,-1.905) D11(12.065,-1.905) D12(10.795,-1.905) D13(9.525,-1.905) D14(8.255,-1.905) D15(6.985,-1.905) D16(5.715,-1.905) D17(4.445,-1.905) D18(3.175,-1.905) D19(1.905,-1.905) D20(0.635,-1.905) D21(-0.635,-1.905) D22(-1.905,-1.905) D23(-3.175,-1.905) D24(-4.445,-1.905) D25(-5.715,-1.905) D26(-6.985,-1.905) D27(-8.255,-1.905) D28(-9.525,-1.905) D29(-10.795,-1.905) D30(-12.065,-1.905) D31(-13.335,-1.905) D32(-14.605,-1.905) D33(-15.875,-1.905) D34(-17.145,-1.905) D35(-18.415,-1.905) D36(-19.685,-1.905) D37(-20.955,-1.905) D38(-22.225,-1.905) D39(-23.495,-1.905) D40(-24.765,-1.905) E1(24.765,-0.635) E2(23.495,-0.635) E3(22.225,-0.635) E4(20.955,-0.635) E5(19.685,-0.635) E6(18.415,-0.635) E7(17.145,-0.635) E8(15.875,-0.635) E9(14.605,-0.635) E10(13.335,-0.635) E11(12.065,-0.635) E12(10.795,-0.635) E13(9.525,-0.635) E14(8.255,-0.635) E15(6.985,-0.635) E16(5.715,-0.635) E17(4.445,-0.635) E18(3.175,-0.635) E19(1.905,-0.635) E20(0.635,-0.635) E21(-0.635,-0.635) E22(-1.905,-0.635) E23(-3.175,-0.635) E24(-4.445,-0.635) E25(-5.715,-0.635) E26(-6.985,-0.635) E27(-8.255,-0.635) E28(-9.525,-0.635) E29(-10.795,-0.635) E30(-12.065,-0.635) E31(-13.335,-0.635) E32(-14.605,-0.635) E33(-15.875,-0.635) E34(-17.145,-0.635) E35(-18.415,-0.635) E36(-19.685,-0.635) E37(-20.955,-0.635) E38(-22.225,-0.635) E39(-23.495,-0.635) E40(-24.765,-0.635) F1(24.765,0.635) F2(23.495,0.635) F3(22.225,0.635) F4(20.955,0.635) F5(19.685,0.635) F6(18.415,0.635) F7(17.145,0.635) F8(15.875,0.635) F9(14.605,0.635) F10(13.335,0.635) F11(12.065,0.635) F12(10.795,0.635) F13(9.525,0.635) F14(8.255,0.635) F15(6.985,0.635) F16(5.715,0.635) F17(4.445,0.635) F18(3.175,0.635) F19(1.905,0.635) F20(0.635,0.635) F21(-0.635,0.635) F22(-1.905,0.635) F23(-3.175,0.635) F24(-4.445,0.635) F25(-5.715,0.635) F26(-6.985,0.635) F27(-8.255,0.635) F28(-9.525,0.635) F29(-10.795,0.635) F30(-12.065,0.635) F31(-13.335,0.635) F32(-14.605,0.635) F33(-15.875,0.635) F34(-17.145,0.635) F35(-18.415,0.635) F36(-19.685,0.635) F37(-20.955,0.635) F38(-22.225,0.635) F39(-23.495,0.635) F40(-24.765,0.635) G1(24.765,1.905) G2(23.495,1.905) G3(22.225,1.905) G4(20.955,1.905) G5(19.685,1.905) G6(18.415,1.905) G7(17.145,1.905) G8(15.875,1.905) G9(14.605,1.905) G10(13.335,1.905) G11(12.065,1.905) G12(10.795,1.905) G13(9.525,1.905) G14(8.255,1.905) G15(6.985,1.905) G16(5.715,1.905) G17(4.445,1.905) G18(3.175,1.905) G19(1.905,1.905) G20(0.635,1.905) G21(-0.635,1.905) G22(-1.905,1.905) G23(-3.175,1.905) G24(-4.445,1.905) G25(-5.715,1.905) G26(-6.985,1.905) G27(-8.255,1.905) G28(-9.525,1.905) G29(-10.795,1.905) G30(-12.065,1.905) G31(-13.335,1.905) G32(-14.605,1.905) G33(-15.875,1.905) G34(-17.145,1.905) G35(-18.415,1.905) G36(-19.685,1.905) G37(-20.955,1.905) G38(-22.225,1.905) G39(-23.495,1.905) G40(-24.765,1.905) H1(24.765,3.175) H2(23.495,3.175) H3(22.225,3.175) H4(20.955,3.175) H5(19.685,3.175) H6(18.415,3.175) H7(17.145,3.175) H8(15.875,3.175) H9(14.605,3.175) H10(13.335,3.175) H11(12.065,3.175) H12(10.795,3.175) H13(9.525,3.175) H14(8.255,3.175) H15(6.985,3.175) H16(5.715,3.175) H17(4.445,3.175) H18(3.175,3.175) H19(1.905,3.175) H20(0.635,3.175) H21(-0.635,3.175) H22(-1.905,3.175) H23(-3.175,3.175) H24(-4.445,3.175) H25(-5.715,3.175) H26(-6.985,3.175) H27(-8.255,3.175) H28(-9.525,3.175) H29(-10.795,3.175) H30(-12.065,3.175) H31(-13.335,3.175) H32(-14.605,3.175) H33(-15.875,3.175) H34(-17.145,3.175) H35(-18.415,3.175) H36(-19.685,3.175) H37(-20.955,3.175) H38(-22.225,3.175) H39(-23.495,3.175) H40(-24.765,3.175) J1(24.765,4.445) J2(23.495,4.445) J3(22.225,4.445) J4(20.955,4.445) J5(19.685,4.445) J6(18.415,4.445) J7(17.145,4.445) J8(15.875,4.445) J9(14.605,4.445) J10(13.335,4.445) J11(12.065,4.445) J12(10.795,4.445) J13(9.525,4.445) J14(8.255,4.445) J15(6.985,4.445) J16(5.715,4.445) J17(4.445,4.445) J18(3.175,4.445) J19(1.905,4.445) J20(0.635,4.445) J21(-0.635,4.445) J22(-1.905,4.445) J23(-3.175,4.445) J24(-4.445,4.445) J25(-5.715,4.445) J26(-6.985,4.445) J27(-8.255,4.445) J28(-9.525,4.445) J29(-10.795,4.445) J30(-12.065,4.445) J31(-13.335,4.445) J32(-14.605,4.445) J33(-15.875,4.445) J34(-17.145,4.445) J35(-18.415,4.445) J36(-19.685,4.445) J37(-20.955,4.445) J38(-22.225,4.445) J39(-23.495,4.445) J40(-24.765,4.445) K1(24.765,5.715) K2(23.495,5.715) K3(22.225,5.715) K4(20.955,5.715) K5(19.685,5.715) K6(18.415,5.715) K7(17.145,5.715) K8(15.875,5.715) K9(14.605,5.715) K10(13.335,5.715) K11(12.065,5.715) K12(10.795,5.715) K13(9.525,5.715) K14(8.255,5.715) K15(6.985,5.715) K16(5.715,5.715) K17(4.445,5.715) K18(3.175,5.715) K19(1.905,5.715) K20(0.635,5.715) K21(-0.635,5.715) K22(-1.905,5.715) K23(-3.175,5.715) K24(-4.445,5.715) K25(-5.715,5.715) K26(-6.985,5.715) K27(-8.255,5.715) K28(-9.525,5.715) K29(-10.795,5.715) K30(-12.065,5.715) K31(-13.335,5.715) K32(-14.605,5.715) K33(-15.875,5.715) K34(-17.145,5.715) K35(-18.415,5.715) K36(-19.685,5.715) K37(-20.955,5.715) K38(-22.225,5.715) K39(-23.495,5.715) K40(-24.765,5.715) L1(24.765,6.985) L2(23.495,6.985) L3(22.225,6.985) L4(20.955,6.985) L5(19.685,6.985) L6(18.415,6.985) L7(17.145,6.985) L8(15.875,6.985) L9(14.605,6.985) L10(13.335,6.985) L11(12.065,6.985) L12(10.795,6.985) L13(9.525,6.985) L14(8.255,6.985) L15(6.985,6.985) L16(5.715,6.985) L17(4.445,6.985) L18(3.175,6.985) L19(1.905,6.985) L20(0.635,6.985) L21(-0.635,6.985) L22(-1.905,6.985) L23(-3.175,6.985) L24(-4.445,6.985) L25(-5.715,6.985) L26(-6.985,6.985) L27(-8.255,6.985) L28(-9.525,6.985) L29(-10.795,6.985) L30(-12.065,6.985) L31(-13.335,6.985) L32(-14.605,6.985) L33(-15.875,6.985) L34(-17.145,6.985) L35(-18.415,6.985) L36(-19.685,6.985) L37(-20.955,6.985) L38(-22.225,6.985) L39(-23.495,6.985) L40(-24.765,6.985) M1(24.765,8.255) M2(23.495,8.255) M3(22.225,8.255) M4(20.955,8.255) M5(19.685,8.255) M6(18.415,8.255) M7(17.145,8.255) M8(15.875,8.255) M9(14.605,8.255) M10(13.335,8.255) M11(12.065,8.255) M12(10.795,8.255) M13(9.525,8.255) M14(8.255,8.255) M15(6.985,8.255) M16(5.715,8.255) M17(4.445,8.255) M18(3.175,8.255) M19(1.905,8.255) M20(0.635,8.255) M21(-0.635,8.255) M22(-1.905,8.255) M23(-3.175,8.255) M24(-4.445,8.255) M25(-5.715,8.255) M26(-6.985,8.255) M27(-8.255,8.255) M28(-9.525,8.255) M29(-10.795,8.255) M30(-12.065,8.255) M31(-13.335,8.255) M32(-14.605,8.255) M33(-15.875,8.255) M34(-17.145,8.255) M35(-18.415,8.255) M36(-19.685,8.255) M37(-20.955,8.255) M38(-22.225,8.255) M39(-23.495,8.255) M40(-24.765,8.255) Y1(24.765,-8.255) Y2(23.495,-8.255) Y3(22.225,-8.255) Y4(20.955,-8.255) Y5(19.685,-8.255) Y6(18.415,-8.255) Y7(17.145,-8.255) Y8(15.875,-8.255) Y9(14.605,-8.255) Y10(13.335,-8.255) Y11(12.065,-8.255) Y12(10.795,-8.255) Y13(9.525,-8.255) Y14(8.255,-8.255) Y15(6.985,-8.255) Y16(5.715,-8.255) Y17(4.445,-8.255) Y18(3.175,-8.255) Y19(1.905,-8.255) Y20(0.635,-8.255) Y21(-0.635,-8.255) Y22(-1.905,-8.255) Y23(-3.175,-8.255) Y24(-4.445,-8.255) Y25(-5.715,-8.255) Y26(-6.985,-8.255) Y27(-8.255,-8.255) Y28(-9.525,-8.255) Y29(-10.795,-8.255) Y30(-12.065,-8.255) Y31(-13.335,-8.255) Y32(-14.605,-8.255) Y33(-15.875,-8.255) Y34(-17.145,-8.255) Y35(-18.415,-8.255) Y36(-19.685,-8.255) Y37(-20.955,-8.255) Y38(-22.225,-8.255) Y39(-23.495,-8.255) Y40(-24.765,-8.255) Z1(24.765,-6.985) Z2(23.495,-6.985) Z3(22.225,-6.985) Z4(20.955,-6.985) Z5(19.685,-6.985) Z6(18.415,-6.985) Z7(17.145,-6.985) Z8(15.875,-6.985) Z9(14.605,-6.985) Z10(13.335,-6.985) Z11(12.065,-6.985) Z12(10.795,-6.985) Z13(9.525,-6.985) Z14(8.255,-6.985) Z15(6.985,-6.985) Z16(5.715,-6.985) Z17(4.445,-6.985) Z18(3.175,-6.985) Z19(1.905,-6.985) Z20(0.635,-6.985) Z21(-0.635,-6.985) Z22(-1.905,-6.985) Z23(-3.175,-6.985) Z24(-4.445,-6.985) Z25(-5.715,-6.985) Z26(-6.985,-6.985) Z27(-8.255,-6.985) Z28(-9.525,-6.985) Z29(-10.795,-6.985) Z30(-12.065,-6.985) Z31(-13.335,-6.985) Z32(-14.605,-6.985) Z33(-15.875,-6.985) Z34(-17.145,-6.985) Z35(-18.415,-6.985) Z36(-19.685,-6.985) Z37(-20.955,-6.985) Z38(-22.225,-6.985) Z39(-23.495,-6.985) Z40(-24.765,-6.985)
  round 3.2 hole 2.692: ST1(-31.484,2.005) ST2(31.508,2.005)
BAT_TS518_TS621_DUAL
  rect 0.889x2.997 smd: 1(0.75,-4.601) 2(-0.75,-4.601)
BEAD_LAIRD_28C0236
  round 1.829 hole 0.813: 1(-7.493,1.27) 2(7.493,-1.27)
C402-25
  round 0.635 smd: 1(-0.508,0) 2(0.508,0)
CAPR_800_350
  rect 1.524x1.524 hole 1.016: 1(0,0)
  round 1.524 hole 1.016: 2(3.556,0)
CL225
  round 0.305 smd: A1(-5.6,5.6) A2(-4.8,5.6) A3(-4,5.6) A4(-3.2,5.6) A5(-2.4,5.6) A6(-1.6,5.6) A7(-0.8,5.6) A8(0,5.6) A9(0.8,5.6) A10(1.6,5.6) A11(2.4,5.6) A12(3.2,5.6) A13(4,5.6) A14(4.8,5.6) A15(5.6,5.6) B1(-5.6,4.8) B2(-4.8,4.8) B3(-4,4.8) B4(-3.2,4.8) B5(-2.4,4.8) B6(-1.6,4.8) B7(-0.8,4.8) B8(0,4.8) B9(0.8,4.8) B10(1.6,4.8) B11(2.4,4.8) B12(3.2,4.8) B13(4,4.8) B14(4.8,4.8) B15(5.6,4.8) C1(-5.6,4) C2(-4.8,4) C3(-4,4) C4(-3.2,4) C5(-2.4,4) C6(-1.6,4) C7(-0.8,4) C8(0,4) C9(0.8,4) C10(1.6,4) C11(2.4,4) C12(3.2,4) C13(4,4) C14(4.8,4) C15(5.6,4) D1(-5.6,3.2) D2(-4.8,3.2) D3(-4,3.2) D4(-3.2,3.2) D5(-2.4,3.2) D6(-1.6,3.2) D7(-0.8,3.2) D8(0,3.2) D9(0.8,3.2) D10(1.6,3.2) D11(2.4,3.2) D12(3.2,3.2) D13(4,3.2) D14(4.8,3.2) D15(5.6,3.2) E1(-5.6,2.4) E2(-4.8,2.4) E3(-4,2.4) E4(-3.2,2.4) E5(-2.4,2.4) E6(-1.6,2.4) E7(-0.8,2.4) E8(0,2.4) E9(0.8,2.4) E10(1.6,2.4) E11(2.4,2.4) E12(3.2,2.4) E13(4,2.4) E14(4.8,2.4) E15(5.6,2.4) F1(-5.6,1.6) F2(-4.8,1.6) F3(-4,1.6) F4(-3.2,1.6) F5(-2.4,1.6) F6(-1.6,1.6) F7(-0.8,1.6) F8(0,1.6) F9(0.8,1.6) F10(1.6,1.6) F11(2.4,1.6) F12(3.2,1.6) F13(4,1.6) F14(4.8,1.6) F15(5.6,1.6) G1(-5.6,0.8) G2(-4.8,0.8) G3(-4,0.8) G4(-3.2,0.8) G5(-2.4,0.8) G6(-1.6,0.8) G7(-0.8,0.8) G8(0,0.8) G9(0.8,0.8) G10(1.6,0.8) G11(2.4,0.8) G12(3.2,0.8) G13(4,0.8) G14(4.8,0.8) G15(5.6,0.8) H1(-5.6,0) H2(-4.8,0) H3(-4,0) H4(-3.2,0) H5(-2.4,0) H6(-1.6,0) H7(-0.8,0) H8(0,0) H9(0.8,0) H10(1.6,0) H11(2.4,0) H12(3.2,0) H13(4,0) H14(4.8,0) H15(5.6,0) J1(-5.6,-0.8) J2(-4.8,-0.8) J3(-4,-0.8) J4(-3.2,-0.8) J5(-2.4,-0.8) J6(-1.6,-0.8) J7(-0.8,-0.8) J8(0,-0.8) J9(0.8,-0.8) J10(1.6,-0.8) J11(2.4,-0.8) J12(3.2,-0.8) J13(4,-0.8) J14(4.8,-0.8) J15(5.6,-0.8) K1(-5.6,-1.6) K2(-4.8,-1.6) K3(-4,-1.6) K4(-3.2,-1.6) K5(-2.4,-1.6) K6(-1.6,-1.6) K7(-0.8,-1.6) K8(0,-1.6) K9(0.8,-1.6) K10(1.6,-1.6) K11(2.4,-1.6) K12(3.2,-1.6) K13(4,-1.6) K14(4.8,-1.6) K15(5.6,-1.6) L1(-5.6,-2.4) L2(-4.8,-2.4) L3(-4,-2.4) L4(-3.2,-2.4) L5(-2.4,-2.4) L6(-1.6,-2.4) L7(-0.8,-2.4) L8(0,-2.4) L9(0.8,-2.4) L10(1.6,-2.4) L11(2.4,-2.4) L12(3.2,-2.4) L13(4,-2.4) L14(4.8,-2.4) L15(5.6,-2.4) M1(-5.6,-3.2) M2(-4.8,-3.2) M3(-4,-3.2) M4(-3.2,-3.2) M5(-2.4,-3.2) M6(-1.6,-3.2) M7(-0.8,-3.2) M8(0,-3.2) M9(0.8,-3.2) M10(1.6,-3.2) M11(2.4,-3.2) M12(3.2,-3.2) M13(4,-3.2) M14(4.8,-3.2) M15(5.6,-3.2) N1(-5.6,-4) N2(-4.8,-4) N3(-4,-4) N4(-3.2,-4) N5(-2.4,-4) N6(-1.6,-4) N7(-0.8,-4) N8(0,-4) N9(0.8,-4) N10(1.6,-4) N11(2.4,-4) N12(3.2,-4) N13(4,-4) N14(4.8,-4) N15(5.6,-4) P1(-5.6,-4.8) P2(-4.8,-4.8) P3(-4,-4.8) P4(-3.2,-4.8) P5(-2.4,-4.8) P6(-1.6,-4.8) P7(-0.8,-4.8) P8(0,-4.8) P9(0.8,-4.8) P10(1.6,-4.8) P11(2.4,-4.8) P12(3.2,-4.8) P13(4,-4.8) P14(4.8,-4.8) P15(5.6,-4.8) R1(-5.6,-5.6) R2(-4.8,-5.6) R3(-4,-5.6) R4(-3.2,-5.6) R5(-2.4,-5.6) R6(-1.6,-5.6) R7(-0.8,-5.6) R8(0,-5.6) R9(0.8,-5.6) R10(1.6,-5.6) R11(2.4,-5.6) R12(3.2,-5.6) R13(4,-5.6) R14(4.8,-5.6) R15(5.6,-5.6)
CON_AMP_U95_T_1Y1_100A
  round 1.651 hole 1.041: 1(1.1,-3.1) 2(-3.4,-12.79) 3(-10.6,-12.79) 4(-17.9,-7.6) 5(-17.9,3.1) 6(-17.9,12.1) 7(-17.9,21.1) 8(-17.9,30.1) 9(1.1,34.6) 10(1.1,25.6) 11(1.1,16.6) 12(1.1,7.6)
CON_HR_ZX62D_AB_5P8
  rect 0.406x1.346 smd: 1(-1.3,0) 2(-0.65,0) 3(0,0) 4(0.65,0) 5(1.3,0)
  oval 1.219x1.93 hole 0.813x1.524: 6(4.089,-2.802) 9(-4.089,-2.802)
  rect 1.803x1.905 smd: 7(1.156,-2.802) 8(-1.156,-2.802)
  oval 1.067x1.27 hole 0.66x0.838: 10(-2.226,0.323) 11(2.226,0.323)
CON_MOL_10P_5025700893
  rect 0.8x1.5 smd: 1(0,0) 2(1.1,0) 3(2.2,0) 4(3.3,0) 5(4.4,0) 6(5.5,0) 7(6.6,0) 8(7.7,0)
  rect 1.4x1.7 smd: 9(9.15,2.9) 10(-3.75,2.9)
  rect 1.143x1.499 smd: 11(9.275,-6.85)
  rect 1.499x1.143 smd: 12(8.7,-11.575) 13(2.1,-11.575) 14(-0.2,-11.575)
CON_MOL_5569_6P
  round 3.937 hole 3.175: (7.283,-0.009) (7.283,-8.391)
  round 2.794 hole 1.803: 1(0,0) 2(0,-4.2) 3(0,-8.4) 4(-5.5,0) 5(-5.5,-4.2) 6(-5.5,-8.4)
CON_SAMTEC_UEC5_UCC8
  round 3.023 hole 3.023 unplated: (-13.169,-8.23) (22.619,-8.23)
  round 1.118 hole 0.762: (-0.5,-1.675) (9.95,-1.675)
  round 1.549 hole 1.194: (-0.27,-13.1) (9.73,-13.1)
  round 0.889 hole 0.889 unplated: (0,0) (0.005,-14.55) (9.45,0.4) (9.455,-14.55)
  rect 0.508x1.143 smd: 1(1.13,-16.11) 2(1.93,-16.11) 3(2.73,-16.11) 4(3.53,-16.11) 5(4.33,-16.11) 6(5.13,-16.11) 7(5.93,-16.11) 8(6.73,-16.11) 9(7.53,-16.11) 10(8.33,-16.11)
  rect 0.305x1.092 smd: A1(0.23,3.85) A4(1.73,3.85) A7(3.23,3.85) A10(4.73,3.85) A13(6.23,3.85) A16(7.73,3.85) A19(9.23,3.85)
  rect 0.305x0.889 smd: A2(0.73,3.95) A3(1.23,3.95) A5(2.23,3.95) A6(2.73,3.95) A8(3.73,3.95) A9(4.23,3.95) A11(5.23,3.95) A12(5.73,3.95) A14(6.73,3.95) A15(7.23,3.95) A17(8.23,3.95) A18(8.73,3.95) B1(0.23,2.35) B2(0.73,2.35) B3(1.23,2.35) B4(1.73,2.35) B5(2.23,2.35) B6(2.73,2.35) B7(3.23,2.35) B8(3.73,2.35) B9(4.23,2.35) B10(4.73,2.35) B11(5.23,2.35) B12(5.73,2.35) B13(6.23,2.35) B14(6.73,2.35) B15(7.23,2.35) B16(7.73,2.35) B17(8.23,2.35) B18(8.73,2.35) B19(9.23,2.35)
DGS_MSOP_10
  rect 1.016x0.305 smd: 1(-2.172,1.001) 2(-2.172,0.5) 3(-2.172,0) 4(-2.172,-0.5) 5(-2.172,-1.001) 6(2.172,-1.001) 7(2.172,-0.5) 8(2.172,0) 9(2.172,0.5) 10(2.172,1.001)
DIGILENT_USB_JTAG_2_NC
  rect 3.556x2.997 smd: 1(-7.5,-9.75) 2(-2.5,-9.75) 3(2.5,-9.75) 4(7.5,-9.75) 8(7.5,9.75) 9(2.5,9.75) 10(-2.5,9.75) 11(-7.5,9.75)
  rect 2.997x3.556 smd: 5(10.25,-5) 6(10.25,0) 7(10.25,5) 12(-10.5,2.5) 13(-10.5,-2.5)
DRY_6_SON
  rect 0.305x0.533 smd: 1(-0.5,-0.392) 2(0,-0.392) 3(0.5,-0.392) 4(0.5,0.392) 5(0,0.392) 6(-0.5,0.392)
EMI_CAGE_175X225
  rect 2.54x5.334 smd: 1(-1.016,-3.327) 2(-1.016,-16.027) 3(-1.016,-28.727) 4(-1.016,-41.427) 9(58.471,-41.427) 10(58.471,-28.727) 11(58.471,-16.027) 12(58.471,-3.327)
  rect 5.334x2.54 smd: 5(9.677,-45.771) 6(22.377,-45.771) 7(35.077,-45.771) 8(47.777,-45.771) 13(47.777,1.016) 14(35.077,1.016) 15(22.377,1.016) 16(9.677,1.016)
FBGA168_13_5X13_5MM
  round 0.406 smd: A2(-5,6) A3(-4,6) A4(-3,6) A5(-2,6) A6(-1,6) A7(0,6) A8(1,6) A9(2,6) A10(3,6) A11(4,6) A12(5.001,6.002) A13(6.001,6.002) B1(-6,5) B2(-5,5) B3(-4,5) B4(-3,5) B5(-2,5) B6(-1,5) B7(0,5) B8(1,5) B9(2,5) B10(3,5) B11(4,5) B12(5.001,5.001) B13(6.001,5.001) C1(-6,4) C2(-5,4) C3(-4,4) C4(-3,4) C5(-2,4) C6(-1,4) C7(0,4) C8(1,4) C9(2,4) C10(3,4) C11(4,4) C12(5.001,4.001) C13(6.001,4.001) D1(-6,3) D2(-5,3) D3(-4,3) D4(-3,3) D5(-2,3) D6(-1,3) D7(0,3) D8(1,3) D9(2,3) D10(3,3) D11(4,3) D12(5.001,3.001) D13(6.001,3.001) E1(-6,2) E2(-5,2) E3(-4,2) E4(-3,2) E5(-2,2) E6(-1,2) E7(0,2) E8(1,2) E9(2,2) E10(3,2) E11(4,2) E12(5.001,2.001) E13(6.001,2.001) F1(-6,1) F2(-5,1) F3(-4,1) F4(-3,1) F5(-2,1) F6(-1,1) F7(0,1) F8(1,1) F9(2,1) F10(3,1) F11(4,1) F12(5.001,1.001) F13(6.001,1.001) G1(-6,0) G2(-5,0) G3(-4,0) G4(-3,0) G5(-2,0) G6(-1,0) G7(0,0) G8(1,0) G9(2,0) G10(3,0) G11(4,0) G12(5.001,0.001) G13(6.001,0.001) H1(-6,-1) H2(-5,-1) H3(-4,-1) H4(-3,-1) H5(-2,-1) H6(-1,-1) H7(0,-1) H8(1,-1) H9(2,-1) H10(3,-1) H11(4,-1) H12(5.001,-0.998) H13(6.001,-0.998) J1(-6,-2) J2(-5,-2) J3(-4,-2) J4(-3,-2) J5(-2,-2) J6(-1,-2) J7(0,-2) J8(1,-2) J9(2,-2) J10(3,-2) J11(4,-2) J12(5.001,-1.998) J13(6.001,-1.998) K1(-6,-3) K2(-5,-3) K3(-4,-3) K4(-3,-3) K5(-2,-3) K6(-1,-3) K7(0,-3) K8(1,-3) K9(2,-3) K10(3,-3) K11(4,-3) K12(5.001,-2.998) K13(6.001,-2.998) L1(-6,-4) L2(-5,-4) L3(-4,-4) L4(-3,-4) L5(-2,-4) L6(-1,-4) L7(0,-4) L8(1,-4) L9(2,-4) L10(3,-4) L11(4,-4) L12(5.001,-3.998) L13(6.001,-3.998) M1(-6,-5) M2(-5,-5) M3(-4,-5) M4(-3,-5) M5(-2,-5) M6(-1,-5) M7(0,-5) M8(1,-5) M9(2,-5) M10(3,-5) M11(4,-5) M12(5.001,-4.998) M13(6.001,-4.998) N1(-6,-6) N2(-5,-6) N3(-4,-6) N4(-3,-6) N5(-2,-6) N6(-1,-6) N7(0,-6) N8(1,-6) N9(2,-6) N10(3,-6) N11(4,-6) N12(5.001,-5.998) N13(6.001,-5.998)
HDR_1X2
  rect 1.524x1.524 hole 1.016: 1(0,0)
  round 1.524 hole 1.016: 2(2.54,0)
HDR_1X3
  rect 1.524x1.524 hole 1.016: 1(0,0)
  round 1.524 hole 1.016: 2(2.54,0) 3(5.08,0)
HDR_1X3_LOCK_MOLEX
  rect 1.524x1.524 hole 1.016: 1(0,0)
  round 1.524 hole 1.016: 2(0,-2.54) 3(0,-5.08)
HDR_1X4
  rect 1.524x1.524 hole 1.016: 1(0,0)
  round 1.524 hole 1.016: 2(2.54,0) 3(5.08,0) 4(7.62,0)
HDR_1X6
  rect 1.524x1.524 hole 1.016: 1(0,0)
  round 1.524 hole 1.016: 2(2.54,0) 3(5.08,0) 4(7.62,0) 5(10.16,0) 6(12.7,0)
HDR_2X4
  rect 1.524x1.524 hole 1.016: 1(0,0)
  round 1.524 hole 1.016: 2(0,2.54) 3(2.54,0) 4(2.54,2.54) 5(5.08,0) 6(5.08,2.54) 7(7.62,0) 8(7.62,2.54)
HDR_2X6
  rect 1.524x1.524 hole 1.016: 1(0,0)
  round 1.524 hole 1.016: 2(0,2.54) 3(2.54,0) 4(2.54,2.54) 5(5.08,0) 6(5.08,2.54) 7(7.62,0) 8(7.62,2.54) 9(10.16,0) 10(10.16,2.54) 11(12.7,0) 12(12.7,2.54)
HDR_BOX_2X8
  rect 1.524x1.524 hole 1.016: 1(0,0)
  round 1.524 hole 1.016: 2(0,2.54) 3(2.54,0) 4(2.54,2.54) 5(5.08,0) 6(5.08,2.54) 7(7.62,0) 8(7.62,2.54) 9(10.16,0) 10(10.16,2.54) 11(12.7,0) 12(12.7,2.54) 13(15.24,0) 14(15.24,2.54) 15(17.78,0) 16(17.78,2.54)
HDR_F2X6_PMOD
  rect 1.524x1.524 hole 1.016: 1(6.35,2.54)
  round 1.524 hole 1.016: 2(6.35,0) 3(3.81,2.54) 4(3.81,0) 5(1.27,2.54) 6(1.27,0) 7(-1.27,2.54) 8(-1.27,0) 9(-3.81,2.54) 10(-3.81,0) 11(-6.35,2.54) 12(-6.35,0)
HPQFN_19_A
  custom 0.089x0.089 smd: 1(-0.727,1.55) 2(-1.121,0.55) 3(-1.121,-0.45) 4(-1.121,-1.45) 5(-1.121,-2.45) 6(1.121,-1.95) 7(1.121,-0.95) 8(1.121,0.05) 9(1.121,1.05) 10(1.68,1.55) 11(1.224,2.8) 12(0.724,2.8) 13(0.224,2.8) 14(-0.276,2.8) 15(-0.776,2.8) 16(-1.276,2.8)
  rect 1.295x1.118 smd: 17(0,4.25)
  rect 1.905x1.27 smd: 18(-1.575,-4.214) 19(1.575,-4.214)
HSMF_C15X
  rect 1.499x0.991 smd: 1(-1.753,0.699) 2(1.753,0.699) 3(-1.753,-0.699) 4(1.753,-0.699)
IND_74479887310
  rect 0.813x2.21 smd: 1(-1.001,0) 2(1.001,0)
IND_COIL_CLB1108_4
  rect 7.01x3.099 smd: 1(-2.15,7.656) 2(2.15,11.252) 3(-2.15,-1.361) 4(2.15,2.261) 5(-2.15,-10.352) 6(2.15,-6.756) 7(-2.15,-19.369) 8(2.15,-15.773)
IND_IHLP2525
  rect 1.829x3.429 smd: 1(-2.769,0) 2(2.769,0)
IND_LAIRD_28F0121_1SR_10
  rect 1.473x2.769 smd: 1(0,-4.013) 2(0,4.013)
IND_VLS252012ET_3R3M
  rect 0.838x2.007 smd: 1(-0.825,0) 2(0.825,0)
IND_WURTH_1210
  rect 2.896x5.41 smd: 1(-4.95,0) 2(4.95,0)
IND_WURTH_2828
  rect 3.2x1.016 smd: 1(0,-1.1) 2(0,1.1)
IND_WURTH_4838
  rect 5.309x2.007 smd: 1(0,1.75) 2(0,-1.75)
IND_WURTH_7040
  rect 2.692x2.21 smd: 1(-2.55,0) 2(2.55,0)
LED_0603
  rect 0.787x0.787 smd: 1(-0.749,0) 2(0.749,0)
MAX6643_QSOP16
  rect 1.651x0.33 smd: 1(-2.685,2.223) 2(-2.685,1.587) 3(-2.685,0.953) 4(-2.685,0.318) 5(-2.685,-0.318) 6(-2.685,-0.953) 7(-2.685,-1.587) 8(-2.685,-2.223) 9(2.685,-2.223) 10(2.685,-1.587) 11(2.685,-0.953) 12(2.685,-0.318) 13(2.685,0.318) 14(2.685,0.953) 15(2.685,1.587) 16(2.685,2.223)
